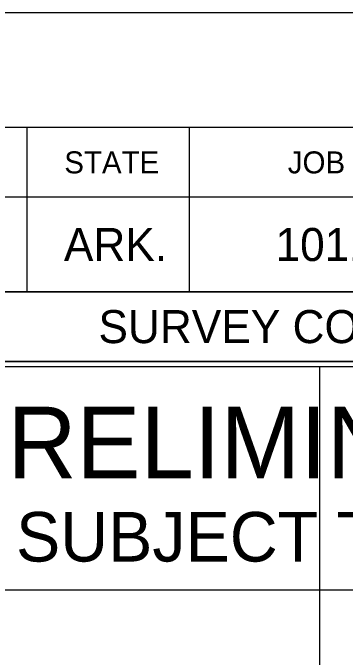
# Model space of a CAD drawing. Extents: x -0.64 to 1.42, y 0 to 0.92.
# Drawn here: x 1.2392 to 1.2995, y 0.7997 to 0.9167 of the extents above; entities that cross this region are included whole.
import ezdxf

# ---------------------------------------------------------------- set-up
doc = ezdxf.new("R2010")
doc.units = 0
for name, color, linetype in [('SHET_Annotations', 7, 'Continuous'), ('SHET_Border-Lines', 7, 'Continuous'), ('SHET_Border-Text', 7, 'Continuous'), ('SHET_Stamp-Prelim', 7, 'Continuous'), ('SHET_Stamp-Seal', 7, 'Continuous')]:
    doc.layers.add(name, color=color, linetype=linetype)

msp = doc.modelspace()

# ---------------------------------------------------------------- linework, layer by layer
at = {"layer": 'SHET_Border-Lines'}
for p, q in [((1.24173, 0.89583), (1.24173, 0.86601)), ((1.27123, 0.89583), (1.27123, 0.86601)), ((1.39583, 0.8832), (1.21266, 0.8832)), ((1.39583, 0.86601), (1.21266, 0.86601)), ((1.22524, 0.86601), (1.39583, 0.86601)), ((1.39583, 0.85338), (1.12962, 0.85338))]:
    msp.add_line(p, q, dxfattribs=at)
for points in [[(0, 0), (1.41667, 0), (1.41667, 0.91667), (0, 0.91667)], [(0.04167, 0.02083), (1.39583, 0.02083), (1.39583, 0.89583), (0.04167, 0.89583)], [(1.12962, 0.85338), (1.39583, 0.85338), (1.39583, 0.89583), (1.12962, 0.89583)]]:
    msp.add_lwpolyline(points, close=True, dxfattribs=at)
at = {"layer": 'SHET_Stamp-Prelim'}
msp.add_lwpolyline([(1.21366, 0.81193), (1.39483, 0.81193), (1.39483, 0.85238), (1.21366, 0.85238)], close=True, dxfattribs=at)
at = {"layer": 'SHET_Stamp-Seal'}
msp.add_lwpolyline([(1.29483, 0.75238), (1.39483, 0.75238), (1.39483, 0.85238), (1.29483, 0.85238)], close=True, dxfattribs=at)

# ---------------------------------------------------------------- texts
at = {"layer": 'SHET_Annotations'}
for s, p in [('ARK.', (1.24847, 0.87161)), ('101189', (1.28687, 0.87161)), ('SURVEY CONTROL DETAILS', (1.25474, 0.8567))]:
    msp.add_text(s, height=0.006, dxfattribs=at).set_placement(p)
at = {"layer": 'SHET_Border-Text'}
for s, p in [('STATE', (1.24854, 0.88752)), ('JOB NO.', (1.2891, 0.88752))]:
    msp.add_text(s, height=0.004, dxfattribs=at).set_placement(p)
at = {"layer": 'SHET_Stamp-Prelim'}
for s, height, p in [('PRELIMINARY', 0.013, (1.22663, 0.83215)), ('SUBJECT TO REVISION', 0.009, (1.23978, 0.81704))]:
    msp.add_text(s, height=height, dxfattribs=at).set_placement(p)

doc.saveas('drawing.dxf')
